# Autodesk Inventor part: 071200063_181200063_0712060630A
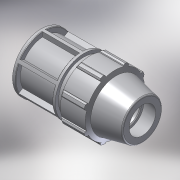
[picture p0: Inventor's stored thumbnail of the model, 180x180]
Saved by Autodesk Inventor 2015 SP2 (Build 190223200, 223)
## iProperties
Created: 2017-02
Part Number: 071200063_181200063_0712060630A
Material: PVC-Piping
Description: PLASSON END PLUG 63
Document SubType Name: Modeling
Designer: KIM
Mass: 92.6774 g
Surface Area: 199.44 cm^2
Volume: 66.1981 cm^3
Density: 1.4 g/cm^3
Appearance: Smooth - White
Author: Кирилл
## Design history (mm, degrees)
derived "07120.ipt"
feature "Solid1::07120.ipt"
tag "TaggingFeature1"
body "Solid1"
other parameters: "d2" = 63, "d4" = 20.71429, "d5" = 36.25, "d7" = 113, "d8" = 84.75, "d9" = 20.71429, "d11" = 4.14286, "d12" = 90.4, "d13" = 120 deg, "d14" = 88.2, "d15" = 8 deg, "d16" = 101.7, "d18" = 3.15, "d19" = 35 deg, "d20" = 17.5 deg, "d21" = 105.09, "d23" = 0, "d25" = 360 deg, "d27" = 2.26, "d34" = 5.65, "d36" = 0, "d42" = 36.25, "d43" = 3.39, "d46" = 1.89, "d53" = 1.26, "d55" = 360 deg, "d59" = 43.5, "d64" = 145, "d66" = 14.69, "d67" = 9.04, "d68" = 122, "d_" = 63, "E_" = 113, "H_" = 145, "l_" = 122
